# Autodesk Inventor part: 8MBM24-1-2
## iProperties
Created: 2007-05
Part Number: 8MBM24-1-2
Document SubType Name: Modeling
Designer: Darius
Author: Darius
Translation Standard: STEP AP203
File Name: 8MBM24-1-2.STEP
Preprocessor: SolidWorks 2003240
Postprocessor: Build: 270, Release: 10 SP2 - Date: Mon 09/26/2005
Sent Units: MILLIMETERS
Uncertainty: 1e-05
